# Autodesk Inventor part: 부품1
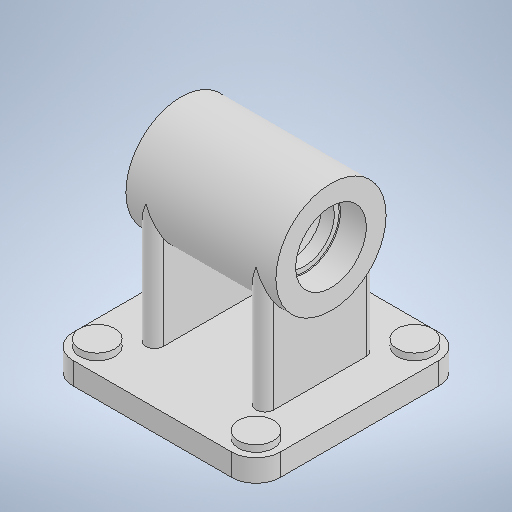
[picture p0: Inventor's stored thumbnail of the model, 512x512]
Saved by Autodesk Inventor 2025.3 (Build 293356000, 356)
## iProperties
Created: 2025-10
Part Number: 부품1
Material: 일반
Document SubType Name: Modeling
Designer: USER
Density: 1 g/cm^3
Appearance: 기본값
Author: USER
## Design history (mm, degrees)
sketch "스케치1"
  geometry: L1 (-34, 0)-(34, 0); L2 (-34, 0)-(-34, 16); L3 (-34, 16)-(-22.3, 16); L4 (-22, 15.7)-(-22, 13.5); L5 (-22, 13.5)-(-16.258, 13.5); L6 (-16.258, 13.5)-(-5, 20); L7 (-5, 20)-(5, 20); L8 (5, 20)-(16.258, 13.5); L9 (16.258, 13.5)-(22, 13.5); L10 (22, 13.5)-(22, 15.7); L11 (22.3, 16)-(34, 16); L12 (34, 16)-(34, 0); L13 (-34, 25)-(34, 25); L14 (-34, 25)-(-34, 16); L15 (34, 25)-(34, 16); A1 r 0.3 centre (-22.3, 15.7) between (-22, 15.7) and (-22.3, 16); A2 r 0.3 centre (22.3, 15.7) between (22.3, 16) and (22, 15.7); 3 further points
  constraints: 30 end point, 6 perpendicular, 4 point on circle, 4 tangent, 3 vertical, 3 vertical alignment, 2 centre point, 2 coincident, 2 midpoint, 2 point on line, 1 equal radius, 1 horizontal, 1 parallel
  dimensions: "d0" = 12 distance between parallel lines of L4 L2; "d1" = 32 diameter of L3 L1; "d2" = 27 diameter of L5 L1; "d3" = 40 diameter of L7 L1; "d4" = 30 deg angle of L1 L6; "d5" = 30 deg angle of L1 L8; "d6" = 10 distance of L7.end L6.end; "d8" = 32 diameter of L11 L1; "d9" = 12 distance between parallel lines of L10 L12; "d10" = 68 distance between parallel lines of L12 L2; "d11" = 50 diameter of L13 L1; "d12" = 0.3 radius of A1 (derived)
revolve "회전1" sketch "스케치1" stored, may be unused: angle "d13" = 90 deg
node "작업 평면1"
sketch "스케치2"
  geometry: L1 (36, -47)-(-36, -47); L2 (-47, -36)-(-47, 36); L3 (-36, 47)-(36, 47); L4 (47, 36)-(47, -36); L5 (47, -47)-(-47, 47); L6 (-47, -47)-(47, 47); A1 r 11 centre (-36, 36) between (-36, 47) and (-47, 36); A2 r 11 centre (36, 36) between (47, 36) and (36, 47); A3 r 11 centre (36, -36) between (36, -47) and (47, -36); A4 r 11 centre (-36, -36) between (-47, -36) and (-36, -47); 1 further point
  constraints: 12 end point, 8 point on circle, 8 point on line, 8 tangent, 4 centre point, 2 equal radius, 2 midpoint, 2 parallel, 1 horizontal, 1 perpendicular
  dimensions: "d15" = 94 distance between parallel lines of L1 L3; "d16" = 94 distance between parallel lines of L2 L4; "d17" = 11 radius of A1; "d18" = 11 radius of A2
extrude "돌출1" join sketch "스케치2" distance "d19" = 10; taper "d20" = 0 deg
sketch "스케치3"
  geometry: L1 (25, -21)-(25, 21); L2 (29, -21)-(29, 21); L3 (21, 21)-(21, -21); L4 (-25, -21)-(-25, 21); L5 (-21, -21)-(-21, 21); L6 (-29, 21)-(-29, -21); A1 r 4 centre (25, -21) between (21, -21) and (29, -21); A2 r 4 centre (25, 21) between (29, 21) and (21, 21); A3 r 4 centre (-25, -21) between (-29, -21) and (-21, -21); A4 r 4 centre (-25, 21) between (-21, 21) and (-29, 21); 7 further points
  constraints: 16 end point, 12 point on circle, 8 tangent, 4 centre point, 2 horizontal alignment, 2 midpoint, 2 parallel, 2 vertical
  dimensions: "d21" = 8 distance between parallel lines of L3 L2; "d22" = 50 distance of point (25, 25) point (25, -25); "d23" = 8 distance between parallel lines of L6 L5; "d24" = 50 distance of point (-25, 25) point (-25, -25); "d25" = 42 distance between parallel lines of L5 L3; "d26" = 21 distance from line of L3 point (0, 0)
extrude "돌출2" join sketch "스케치3" stored distance "d27" = 0; taper "d28" = 0 deg
sketch "스케치4"
  geometry: L1 (-36, -47)-(36, -47) reference; L2 (47, -36)-(47, 36) reference; L3 (-36, -47)-(36, -47) reference; L4 (-47, 36)-(-47, -36) reference; L5 (36, 47)-(-36, 47) reference; L6 (47, -36)-(47, 36) reference; C1 r 8 at (36, -36); C2 r 8 at (-36, -36); C3 r 8 at (-36, 36); C4 r 8 at (36, 36); A1 r 11 centre (36, -36) between (36, -47) and (47, -36) reference; A2 r 11 centre (-36, -36) between (-47, -36) and (-36, -47) reference; A3 r 11 centre (-36, 36) between (-36, 47) and (-47, 36) reference; A4 r 11 centre (36, 36) between (47, 36) and (36, 47) reference; A5 r 11 centre (36, -36) between (36, -47) and (47, -36) reference; 1 further point
  constraints: 4 centre point, 4 coincident
  dimensions: "d29" = 16 diameter of C1; "d30" = 16 diameter of C2; "d31" = 16 diameter of C3; "d32" = 16 diameter of C4
extrude "돌출3" join sketch "스케치4" distance "d33" = 3; taper "d34" = 0 deg
node "솔리드1"
node "투영된 루프1"
other parameters: "d14" = -66
